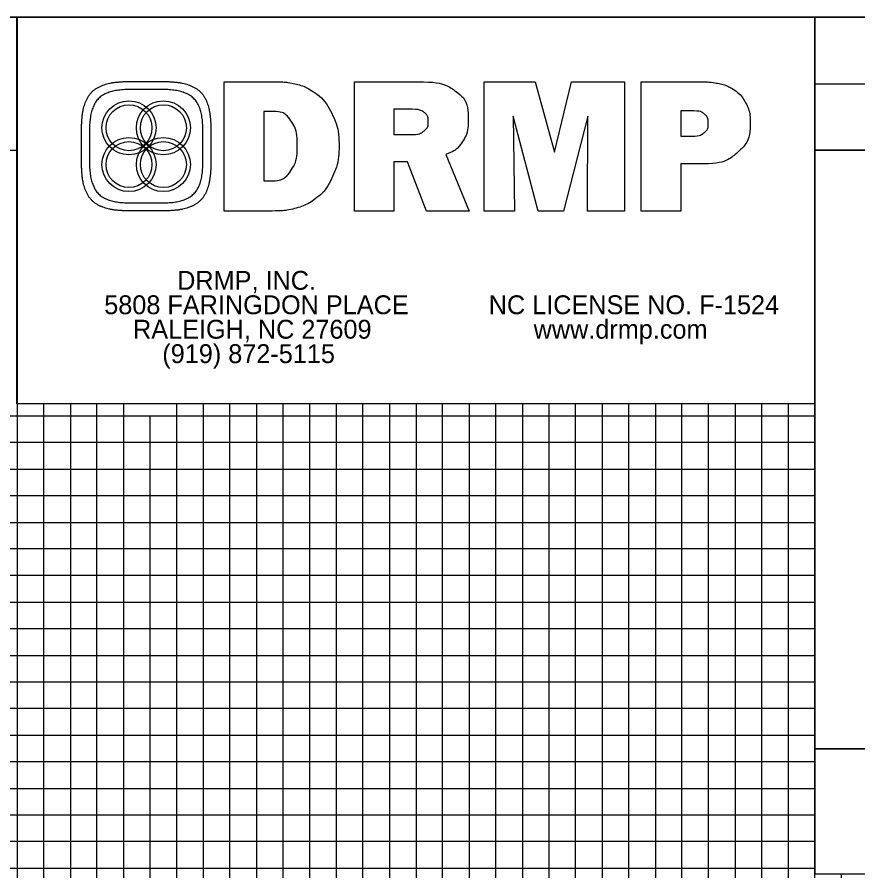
# Model space of a CAD drawing. Extents: x 573078 to 573131.9, y -55221.3 to -55195.5.
# Drawn here: x 573104.514 to 573107.676, y -55203.009 to -55199.798 of the extents above; entities that cross this region are included whole.
import ezdxf

# ---------------------------------------------------------------- set-up
doc = ezdxf.new("R2010")
doc.units = 0
for name, color, linetype in [('Pattern 1', 7, 'Continuous'), ('Pattern 2', 7, 'Continuous'), ('Sheet Clip Boundary CELL', 7, 'Continuous'), ('Sheet Plan CELL', 7, 'Continuous'), ('Sheet Profile CELL', 7, 'Continuous'), ('Sheet Profile Grid Major CELL', 7, 'Continuous'), ('Sheet Profile Grid Middle CELL', 7, 'Continuous'), ('Sheet Profile Grid Minor CELL', 7, 'Continuous'), ('Sheet Sticker Exception Certification CELL', 7, 'Continuous')]:
    doc.layers.add(name, color=color, linetype=linetype)

msp = doc.modelspace()

# ---------------------------------------------------------------- linework, layer by layer
at = {"layer": 'Pattern 1'}
for p, q in [((573104.9289, -55200.041), (573105.0698, -55200.041)), ((573106.2708, -55200.5276), (573106.2708, -55200.0415)), ((573106.2708, -55200.0415), (573106.462, -55200.0415)), ((573106.462, -55200.0415), (573106.5348, -55200.3069)), ((573106.5348, -55200.3069), (573106.599, -55200.0415)), ((573106.599, -55200.0415), (573106.7987, -55200.0415)), ((573106.7987, -55200.0415), (573106.7987, -55200.5276)), ((573105.0612, -55200.0707), (573104.9375, -55200.0707)), ((573106.474, -55200.5276), (573106.3793, -55200.1711)), ((573106.3793, -55200.1711), (573106.3845, -55200.5276)), ((573106.6609, -55200.1711), (573106.5683, -55200.5276)), ((573106.6585, -55200.5276), (573106.6609, -55200.1711)), ((573104.7565, -55200.3543), (573104.7565, -55200.2134)), ((573104.7862, -55200.222), (573104.7862, -55200.3457)), ((573105.2125, -55200.3457), (573105.2125, -55200.222)), ((573105.2423, -55200.2134), (573105.2423, -55200.3543)), ((573104.9375, -55200.497), (573105.0612, -55200.497)), ((573105.0698, -55200.5268), (573104.9289, -55200.5268)), ((573106.3845, -55200.5276), (573106.2708, -55200.5276)), ((573106.5683, -55200.5276), (573106.474, -55200.5276)), ((573106.7987, -55200.5276), (573106.6585, -55200.5276))]:
    msp.add_line(p, q, dxfattribs=at)
for points in [[(573105.4729, -55200.5276), (573105.2924, -55200.5276), (573105.2924, -55200.0415), (573105.4794, -55200.0415)], [(573106.1258, -55200.3152), (573106.2134, -55200.5276), (573106.0537, -55200.5276), (573105.9815, -55200.3432), (573105.9306, -55200.3432), (573105.9306, -55200.5276), (573105.7827, -55200.5276), (573105.7827, -55200.0415), (573106.0202, -55200.0415)], [(573107.0959, -55200.3504), (573107.0096, -55200.3504), (573107.0096, -55200.5276), (573106.8606, -55200.5276), (573106.8606, -55200.0415), (573107.0678, -55200.0415)], [(573105.9993, -55200.1452), (573105.9306, -55200.1452), (573105.9306, -55200.2402), (573106.0014, -55200.2402)], [(573105.4794, -55200.1532), (573105.4414, -55200.1532), (573105.4414, -55200.4139), (573105.4749, -55200.4139)], [(573107.0586, -55200.1513), (573107.0096, -55200.1513), (573107.0096, -55200.2467), (573107.0497, -55200.2467)]]:
    msp.add_lwpolyline(points, dxfattribs=at)
for points, degree in [([(573104.7565, -55200.2134), (573104.7565, -55200.1186), (573104.8341, -55200.041), (573104.9289, -55200.041)], 2), ([(573105.0698, -55200.041), (573105.1646, -55200.041), (573105.2423, -55200.1186), (573105.2423, -55200.2134)], 2), ([(573105.4794, -55200.0415), (573105.5088, -55200.0415), (573105.5352, -55200.0441), (573105.5585, -55200.0493), (573105.5818, -55200.0546), (573105.6021, -55200.0627), (573105.6194, -55200.0736), (573105.6527, -55200.0946), (573105.6786, -55200.1235), (573105.6969, -55200.1603), (573105.7153, -55200.1972), (573105.7245, -55200.2385), (573105.7245, -55200.2843), (573105.7245, -55200.3249), (573105.7164, -55200.3629), (573105.7002, -55200.3983), (573105.684, -55200.4336), (573105.662, -55200.4618), (573105.6341, -55200.4827), (573105.6134, -55200.498), (573105.5899, -55200.5093), (573105.5638, -55200.5166), (573105.5376, -55200.5239), (573105.5074, -55200.5276), (573105.4729, -55200.5276)], 3), ([(573106.0202, -55200.0415), (573106.0838, -55200.0415), (573106.1314, -55200.0533), (573106.1631, -55200.0769), (573106.1948, -55200.1005), (573106.2107, -55200.136), (573106.2107, -55200.1834), (573106.2107, -55200.2163), (573106.2034, -55200.244), (573106.1889, -55200.2666), (573106.1745, -55200.2892), (573106.1534, -55200.3054), (573106.1258, -55200.3152)], 3), ([(573107.0678, -55200.0415), (573107.1002, -55200.0415), (573107.1271, -55200.0435), (573107.1484, -55200.0474), (573107.1698, -55200.0514), (573107.1875, -55200.0578), (573107.2016, -55200.0664), (573107.2245, -55200.0808), (573107.2417, -55200.0989), (573107.2535, -55200.1208), (573107.2652, -55200.1427), (573107.2711, -55200.1676), (573107.2711, -55200.1954), (573107.2711, -55200.2417), (573107.255, -55200.2792), (573107.2229, -55200.3077), (573107.1907, -55200.3362), (573107.1484, -55200.3504), (573107.0959, -55200.3504)], 3), ([(573104.9375, -55200.0707), (573104.8543, -55200.0707), (573104.7862, -55200.1388), (573104.7862, -55200.222)], 2), ([(573105.2125, -55200.222), (573105.2125, -55200.1388), (573105.1444, -55200.0707), (573105.0612, -55200.0707)], 2), ([(573106.0014, -55200.2402), (573106.0187, -55200.2402), (573106.0328, -55200.2358), (573106.0438, -55200.2269), (573106.0547, -55200.218), (573106.0602, -55200.2066), (573106.0602, -55200.1927), (573106.0602, -55200.1768), (573106.0551, -55200.1649), (573106.0449, -55200.157), (573106.0348, -55200.1491), (573106.0196, -55200.1452), (573105.9993, -55200.1452)], 3), ([(573105.4749, -55200.4139), (573105.5028, -55200.4139), (573105.5252, -55200.4019), (573105.542, -55200.378), (573105.5588, -55200.354), (573105.5672, -55200.3221), (573105.5672, -55200.2822), (573105.5672, -55200.2427), (573105.5592, -55200.2114), (573105.5433, -55200.1881), (573105.5275, -55200.1648), (573105.5061, -55200.1532), (573105.4794, -55200.1532)], 3), ([(573107.0497, -55200.2467), (573107.0698, -55200.2467), (573107.0854, -55200.2425), (573107.0966, -55200.234), (573107.1078, -55200.2256), (573107.1134, -55200.2139), (573107.1134, -55200.1988), (573107.1134, -55200.1836), (573107.1087, -55200.1718), (573107.0993, -55200.1636), (573107.09, -55200.1554), (573107.0764, -55200.1513), (573107.0586, -55200.1513)], 3), ([(573104.9289, -55200.5268), (573104.8341, -55200.5268), (573104.7565, -55200.4491), (573104.7565, -55200.3543)], 2), ([(573104.7862, -55200.3457), (573104.7862, -55200.4289), (573104.8543, -55200.497), (573104.9375, -55200.497)], 2), ([(573105.0612, -55200.497), (573105.1444, -55200.497), (573105.2125, -55200.4289), (573105.2125, -55200.3457)], 2), ([(573105.2423, -55200.3543), (573105.2423, -55200.4491), (573105.1646, -55200.5268), (573105.0698, -55200.5268)], 2)]:
    msp.add_open_spline(points, degree=degree, dxfattribs=at)
at = {"layer": 'Pattern 2'}
for centre, radius in [((573104.9347, -55200.2148), 0.1016), ((573105.064, -55200.2148), 0.1016), ((573104.9347, -55200.2148), 0.0864), ((573105.064, -55200.2148), 0.0864), ((573104.9347, -55200.3529), 0.1016), ((573104.9347, -55200.3529), 0.0864), ((573105.064, -55200.3529), 0.1016), ((573105.064, -55200.3529), 0.0864)]:
    msp.add_circle(centre, radius, dxfattribs=at)
at = {"layer": 'Sheet Clip Boundary CELL'}
msp.add_lwpolyline([(573082.5142, -55199.7984), (573107.5142, -55199.7984), (573107.5142, -55203.0194), (573110.5142, -55203.0194), (573110.5142, -55220.2984), (573082.5142, -55220.2984)], close=True, dxfattribs=at)
at = {"layer": 'Sheet Plan CELL'}
msp.add_lwpolyline([(573107.5142, -55201.252), (573104.5134, -55201.252), (573104.5134, -55199.7984), (573107.5142, -55199.7984)], close=True, dxfattribs=at)
at = {"layer": 'Sheet Profile CELL'}
msp.add_line((573107.5142, -55200.0494), (573111.5142, -55200.0494), dxfattribs=at)
for points in [[(573111.5142, -55199.7984), (573081.5142, -55199.7984), (573081.5142, -55220.7984), (573111.5142, -55220.7984)], [(573107.5142, -55199.7984), (573111.5142, -55199.7984), (573111.5142, -55200.2994), (573107.5142, -55200.2994)], [(573107.5142, -55200.2994), (573109.5142, -55200.2994), (573109.5142, -55202.5494), (573107.5142, -55202.5494)]]:
    msp.add_lwpolyline(points, close=True, dxfattribs=at)
at = {"layer": 'Sheet Profile Grid Major CELL'}
for points in [[(573103.5142, -55220.2984), (573103.5142, -55199.7984), (573104.5142, -55199.7984), (573104.5142, -55220.2984)], [(573106.5142, -55201.252), (573106.5142, -55220.2984), (573107.5142, -55220.2984), (573107.5142, -55199.7984)], [(573107.5142, -55201.2984), (573081.5142, -55201.2984), (573081.5142, -55200.2984), (573104.5134, -55200.2984)], [(573105.5142, -55220.2984), (573105.5142, -55201.252)], [(573111.5142, -55203.2984), (573081.5142, -55203.2984), (573081.5142, -55202.2984), (573107.5142, -55202.2984)]]:
    msp.add_lwpolyline(points, dxfattribs=at)
at = {"layer": 'Sheet Profile Grid Middle CELL'}
for points in [[(573106.0142, -55201.252), (573106.0142, -55220.2984), (573107.0142, -55220.2984), (573107.0142, -55201.252)], [(573105.0142, -55220.2984), (573105.0142, -55201.2984)], [(573107.5142, -55201.7984), (573081.5142, -55201.7984), (573081.5142, -55202.7984), (573107.5142, -55202.7984)]]:
    msp.add_lwpolyline(points, dxfattribs=at)
at = {"layer": 'Sheet Profile Grid Minor CELL'}
for points in [[(573104.6142, -55220.2984), (573104.6142, -55201.252)], [(573104.7142, -55201.252), (573104.7142, -55220.2984), (573104.8142, -55220.2984), (573104.8142, -55201.252)], [(573104.9142, -55201.252), (573104.9142, -55220.2984), (573105.1142, -55220.2984), (573105.1142, -55201.252)], [(573105.2142, -55201.252), (573105.2142, -55220.2984), (573105.3142, -55220.2984), (573105.3142, -55201.252)], [(573105.4142, -55201.252), (573105.4142, -55220.2984), (573105.6142, -55220.2984), (573105.6142, -55201.252)], [(573105.7142, -55201.252), (573105.7142, -55220.2984), (573105.8142, -55220.2984), (573105.8142, -55201.252)], [(573105.9142, -55201.252), (573105.9142, -55220.2984), (573106.1142, -55220.2984), (573106.1142, -55201.252)], [(573106.2142, -55201.252), (573106.2142, -55220.2984), (573106.3142, -55220.2984), (573106.3142, -55201.252)], [(573106.4142, -55201.252), (573106.4142, -55220.2984), (573106.6142, -55220.2984), (573106.6142, -55201.252)], [(573106.7142, -55201.252), (573106.7142, -55220.2984), (573106.8142, -55220.2984), (573106.8142, -55201.252)], [(573106.9142, -55201.252), (573106.9142, -55220.2984), (573107.1142, -55220.2984), (573107.1142, -55201.252)], [(573107.2142, -55201.252), (573107.2142, -55220.2984), (573107.3142, -55220.2984), (573107.3142, -55201.252)], [(573107.4142, -55201.252), (573107.4142, -55220.2984), (573107.6142, -55220.2984), (573107.6142, -55203.0194)], [(573107.5142, -55201.3984), (573082.5142, -55201.3984), (573082.5142, -55201.4984), (573107.5142, -55201.4984)], [(573107.5142, -55201.5984), (573082.5142, -55201.5984), (573082.5142, -55201.6984), (573107.5142, -55201.6984)], [(573107.5142, -55201.8984), (573082.5142, -55201.8984), (573082.5142, -55201.9984), (573107.5142, -55201.9984)], [(573107.5142, -55202.0984), (573082.5142, -55202.0984), (573082.5142, -55202.1984), (573107.5142, -55202.1984)], [(573107.5142, -55202.3984), (573082.5142, -55202.3984), (573082.5142, -55202.4984), (573107.5142, -55202.4984)], [(573107.5142, -55202.5984), (573082.5142, -55202.5984), (573082.5142, -55202.5984), (573082.5142, -55202.9984), (573107.5142, -55202.9984)], [(573082.5142, -55202.6984), (573107.5142, -55202.6984)], [(573107.5142, -55202.8984), (573082.5142, -55202.8984)]]:
    msp.add_lwpolyline(points, dxfattribs=at)
at = {"layer": 'Sheet Sticker Exception Certification CELL'}
for p, q in [((573107.5142, -55203.0194), (573107.5142, -55202.5494)), ((573107.5142, -55202.5494), (573111.5149, -55202.5494))]:
    msp.add_line(p, q, dxfattribs=at)

# ---------------------------------------------------------------- texts
at = {"layer": 'Pattern 2'}
for s, height, p in [('DRMP, INC.', 0.07099, (573105.1159, -55200.8238)), ('5808 FARINGDON PLACE', 0.070991, (573104.8416, -55200.9157)), ('NC LICENSE NO. F-1524', 0.070991, (573106.2875, -55200.9157)), ('RALEIGH, NC 27609', 0.070991, (573104.9499, -55201.0076)), ('www.drmp.com', 0.070991, (573106.4564, -55201.0076)), ('(919) 872-5115', 0.070991, (573105.06, -55201.0995))]:
    msp.add_text(s, height=height, rotation=360, dxfattribs=at).set_placement(p)

doc.saveas('drawing.dxf')
